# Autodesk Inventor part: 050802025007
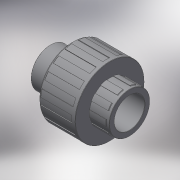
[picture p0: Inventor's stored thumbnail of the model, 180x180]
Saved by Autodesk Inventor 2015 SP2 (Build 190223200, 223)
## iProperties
Created: 2017-10
Part Number: 050802025007
Material: Generic
Description: PLASSON UNION+O RING THR-CEM 25-3/4"
Document SubType Name: Modeling
Designer: KIM
Density: 1 g/cm^3
Appearance: Default
Author: KIM
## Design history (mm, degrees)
derived "050802.ipt"
feature "Solid1::050802.ipt"
tag "TaggingFeature1"
body "Solid1"
other parameters: "d0" = 51, "d3" = 25, "d4" = 24.117, "d6" = 31.25, "d7" = 32, "d8" = 52, "d9" = 19, "d10" = 18, "d11" = 21.25, "d12" = 23.75, "d14" = 13.5, "d15" = 14.25, "d16" = 12.6, "d17" = 1.8, "d19" = 50.96, "d20" = 1.9, "d21" = 1.56, "d25" = 5.2, "d26" = 2.6, "d27" = 19.215, "d28" = 0, "d32" = 5.2, "d33" = 2.6, "d35" = 0, "d39" = 0.25, "d45" = 0.375, "d49" = 360 deg, "d51" = 0.52, "d55" = 360 deg, "d_" = 25, "E_" = 52, "H_" = 39, "l_" = 19, "lt_" = 18, "Z_" = 11, "G_" = 24.117, "d13" = 14, "d24" = 21.35, "d40" = 0.375, "d44" = 0.52
